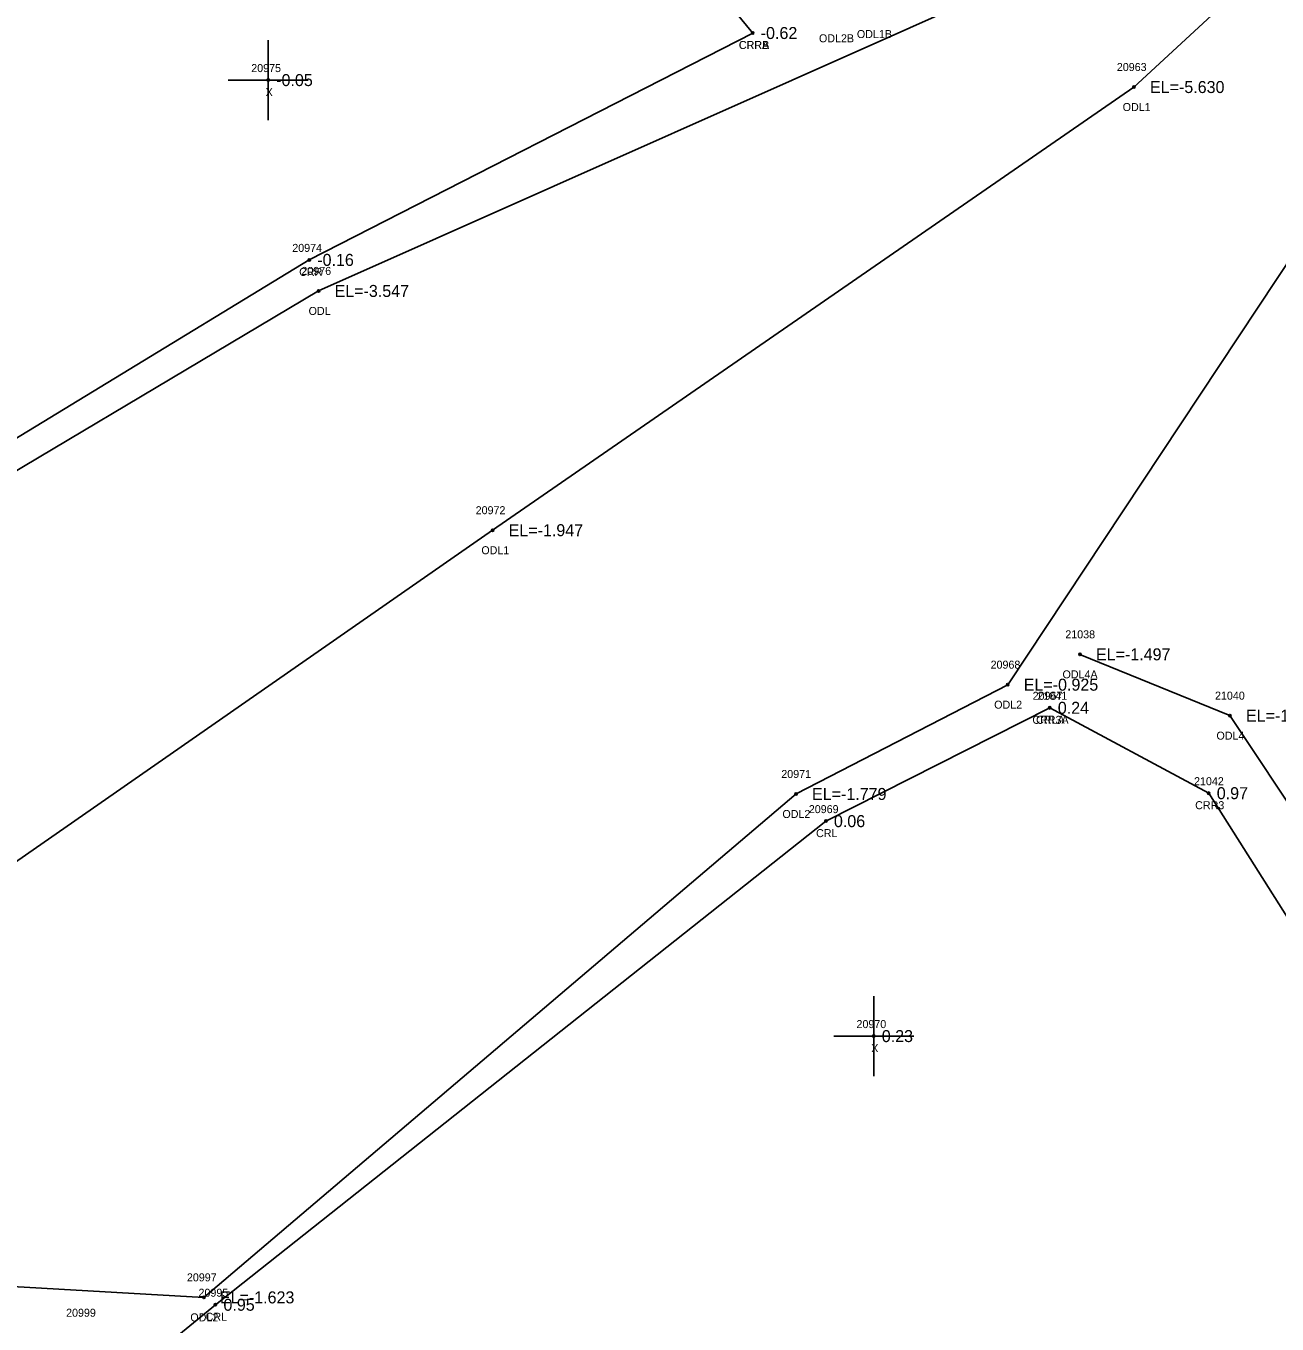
# Model space of a CAD drawing. Extents: x 2608745 to 2610333, y 641917 to 643463.
# Drawn here: x 2609386.5 to 2609542.9, y 642503 to 642665.2 of the extents above; entities that cross this region are included whole.
import ezdxf

# ---------------------------------------------------------------- set-up
doc = ezdxf.new("R2010")
doc.units = 0
for name, color, linetype in [('RD_EX_H2O', 7, 'Continuous'), ('RD_EX_H2O_txCode', 7, 'Continuous'), ('RD_EX_Misc', 7, 'Continuous'), ('RD_EX_Misc_txCode', 7, 'Continuous'), ('RD_EX_TX_H2O_ELEV', 7, 'Continuous'), ('RD_EX_TX_Misc_ELEV', 7, 'Continuous'), ('RD_SMD_Locator', 7, 'Continuous')]:
    doc.layers.add(name, color=color, linetype=linetype)

msp = doc.modelspace()

# ---------------------------------------------------------------- linework, layer by layer
at = {"layer": 'RD_EX_H2O'}
for points in [[(2609918.81, 643009.04), (2609840.99, 642946.19), (2609752.78, 642894.89), (2609679.02, 642833.68), (2609605.53, 642770.83), (2609557.42, 642733.27), (2609539.43, 642701.73), (2609511.68, 642671.53), (2609423.05, 642632.06), (2609369.55, 642600.24), (2609327.57, 642579.96), (2609257.07, 642528.8), (2609194.6, 642443.8), (2609156.56, 642341.27)], [(2609920.46, 642991.11), (2609852.12, 642929.11), (2609767.83, 642874.99), (2609693.3, 642807.6), (2609634.08, 642753.09), (2609556.79, 642686.91), (2609524.97, 642657.54), (2609444.81, 642602.16), (2609373.09, 642552.33), (2609285.68, 642492.71), (2609230.49, 642411.33), (2609205.38, 642280.88)], [(2609940.72, 642981.52), (2609865.8, 642912.86), (2609792.29, 642852.87), (2609723.77, 642786.36), (2609663.25, 642717.18), (2609610.37, 642689.46), (2609581.45, 642670.47), (2609545.26, 642637.18), (2609509.19, 642582.86), (2609482.73, 642569.2), (2609408.72, 642506.3), (2609370.25, 642508.5), (2609327.7, 642455.81), (2609283.83, 642369.21), (2609262.12, 642251.22)], [(2609341.7, 642811.8), (2609340.78, 642806.36), (2609373.72, 642772.7), (2609409.62, 642743.52), (2609461.2, 642683.86), (2609477.32, 642664.29)], [(2609477.32, 642664.29), (2609421.89, 642635.94), (2609369.59, 642604.11), (2609326.85, 642619.9), (2609278.2, 642658.63)], [(2609518.22, 642586.65), (2609536.97, 642578.99), (2609575.62, 642520.95), (2609643.94, 642461.12), (2609713.29, 642393.38), (2609797.14, 642314.29), (2609845.08, 642297.38), (2609901.61, 642240.2), (2609849.12, 642177.48), (2609793.89, 642090.6)], [(2609514.45, 642579.97), (2609486.47, 642565.81), (2609410.17, 642505.38), (2609388.62, 642487.73), (2609394.57, 642463.69), (2609426.91, 642433.05)], [(2609514.45, 642579.97), (2609534.32, 642569.3), (2609569.82, 642513.21), (2609640.11, 642458.03), (2609710.3, 642387.96), (2609794.99, 642310.91), (2609843.78, 642290.31), (2609891.67, 642241.7), (2609844.05, 642181.23), (2609787.66, 642090.39)]]:
    msp.add_lwpolyline(points, dxfattribs=at)
at = {"layer": 'RD_EX_Misc'}
for p, q in [((2609416.76, 642653.41), (2609416.76, 642663.41)), ((2609411.76, 642658.41), (2609421.76, 642658.41)), ((2609492.45, 642533.95), (2609492.45, 642543.95)), ((2609487.45, 642538.95), (2609497.45, 642538.95))]:
    msp.add_line(p, q, dxfattribs=at)
at = {"layer": 'RD_SMD_Locator'}
for centre in [(2609477.32, 642664.29), (2609477.32, 642664.29), (2609416.76, 642658.41), (2609524.97, 642657.54), (2609421.89, 642635.94), (2609423.05, 642632.06), (2609444.81, 642602.16), (2609518.22, 642586.65), (2609509.19, 642582.86), (2609514.45, 642579.97), (2609514.45, 642579.97), (2609536.97, 642578.99), (2609482.73, 642569.2), (2609534.32, 642569.3), (2609486.47, 642565.81), (2609492.45, 642538.95), (2609408.72, 642506.3), (2609410.17, 642505.38)]:
    msp.add_circle(centre, 0.15, dxfattribs=at)

# ---------------------------------------------------------------- texts
at = {"layer": 'RD_EX_H2O_txCode'}
for s, p in [('ODL2B', (2609485.6, 642663.13)), ('ODL1B', (2609490.34, 642663.66)), ('CRRA', (2609475.58, 642662.29)), ('CRRB', (2609475.6, 642662.29)), ('20963', (2609522.83, 642659.54)), ('ODL1', (2609523.56, 642654.54)), ('20974', (2609419.77, 642636.94)), ('CRR', (2609420.63, 642633.94)), ('20976', (2609420.91, 642634.06)), ('ODL', (2609421.81, 642629.06)), ('20972', (2609442.69, 642604.16)), ('ODL1', (2609443.4, 642599.16)), ('21038', (2609516.39, 642588.65)), ('20968', (2609507.05, 642584.86)), ('ODL4A', (2609516.04, 642583.65)), ('20967', (2609512.31, 642580.97)), ('21041', (2609512.9, 642580.97)), ('21040', (2609535.1, 642580.99)), ('ODL2', (2609507.5, 642579.86)), ('CRR3A', (2609512.27, 642577.97)), ('CRLA', (2609512.74, 642577.97)), ('ODL4', (2609535.28, 642575.99)), ('20971', (2609480.89, 642571.2)), ('21042', (2609532.48, 642570.3)), ('CRR3', (2609532.62, 642567.3)), ('ODL2', (2609481.03, 642566.2)), ('20969', (2609484.33, 642566.81)), ('CRL', (2609485.24, 642563.81)), ('20997', (2609406.6, 642508.3)), ('20995', (2609408.05, 642506.38)), ('20999', (2609391.5, 642503.88)), ('ODL2', (2609407.03, 642503.3)), ('CRL', (2609408.94, 642503.38))]:
    msp.add_text(s, height=1, dxfattribs=at).set_placement(p)
at = {"layer": 'RD_EX_Misc_txCode'}
for s, p in [('20975', (2609414.64, 642659.41)), ('X', (2609416.44, 642656.41)), ('20970', (2609490.29, 642539.95)), ('X', (2609492.13, 642536.95))]:
    msp.add_text(s, height=1, dxfattribs=at).set_placement(p)
at = {"layer": 'RD_EX_TX_H2O_ELEV'}
for s, p in [('-0.62', (2609478.32, 642663.54)), ('-0.62', (2609478.32, 642663.54)), ('EL=-5.630', (2609526.97, 642656.79)), ('-0.16', (2609422.89, 642635.19)), ('EL=-3.547', (2609425.05, 642631.31)), ('EL=-1.947', (2609446.81, 642601.41)), ('EL=-1.497', (2609520.22, 642585.9)), ('EL=-0.925', (2609511.19, 642582.11)), ('0.24', (2609515.45, 642579.22)), ('0.24', (2609515.45, 642579.22)), ('EL=-1.931', (2609538.97, 642578.24)), ('EL=-1.779', (2609484.73, 642568.45)), ('0.97', (2609535.32, 642568.55)), ('0.06', (2609487.47, 642565.06)), ('EL=-1.623', (2609410.72, 642505.55)), ('0.95', (2609411.17, 642504.63))]:
    msp.add_text(s, height=1.5, dxfattribs=at).set_placement(p)
at = {"layer": 'RD_EX_TX_Misc_ELEV'}
for s, p in [('-0.05', (2609417.76, 642657.66)), ('0.23', (2609493.45, 642538.2))]:
    msp.add_text(s, height=1.5, dxfattribs=at).set_placement(p)

doc.saveas('drawing.dxf')
